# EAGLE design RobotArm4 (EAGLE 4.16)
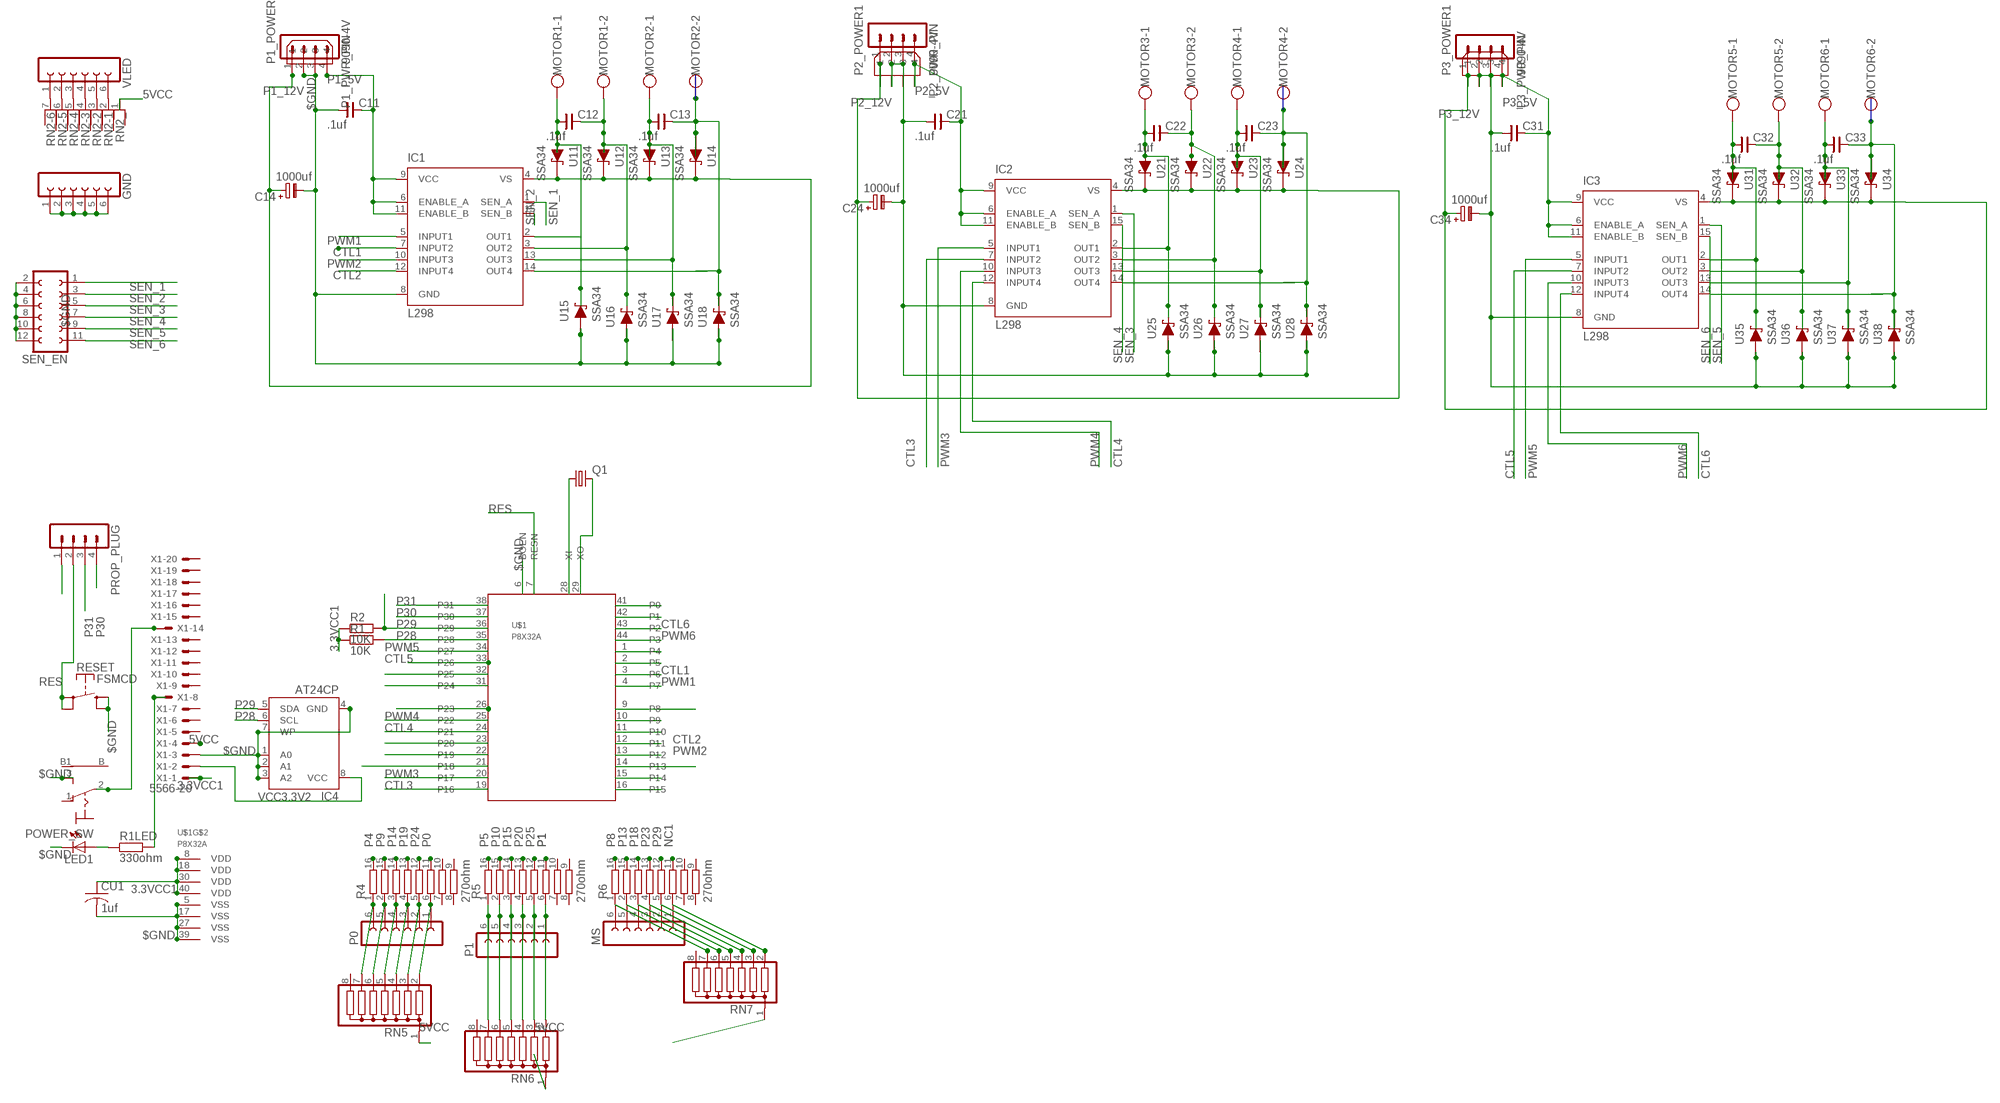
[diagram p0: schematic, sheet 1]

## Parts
C11  .1uf  CNP-1206  [1206]
C12  .1uf  CNP-1206  [1206]
C13  .1uf  CNP-1206  [1206]
C14  1000uf  C-PR-SMD-SV-C  [SV-C]
C21  .1uf  CNP-1206  [1206]
C22  .1uf  CNP-1206  [1206]
C23  .1uf  CNP-1206  [1206]
C24  1000uf  C-PR-SMD-SV-C  [SV-C]
C31  .1uf  CNP-1206  [1206]
C32  .1uf  CNP-1206  [1206]
C33  .1uf  CNP-1206  [1206]
C34  1000uf  C-PR-SMD-SV-C  [SV-C]
CU1  1uf  C-USC1206  [C1206]
GND  FE06-1  [FE06]
IC1  L298  [MULTIWATT-15]
IC2  L298  [MULTIWATT-15]
IC3  L298  [MULTIWATT-15]
IC4  AT24CP  [DIL08]
LED1  LED5MM  [LED5MM]
MOTOR1  W237-102  [W237-102]
MOTOR2  W237-102  [W237-102]
MOTOR3  W237-102  [W237-102]
MOTOR4  W237-102  [W237-102]
MOTOR5  W237-102  [W237-102]
MOTOR6  W237-102  [W237-102]
MS  FE06-1  [FE06]
P0  FE06-1  [FE06]
P1  FE06-1  [FE06]
P1_POWER  9090-4V  [9090-4V]
P1_PWR_PIN  MA04-1  [MA04-1]
P2_POWER1  9090-4V  [9090-4V]
P2_PWR_PIN  MA04-1  [MA04-1]
P3_POWER1  9090-4V  [9090-4V]
P3_PWR_PIN  MA04-1  [MA04-1]
POWER_SW  9070-1W  [9070-1W]
PROP_PLUG  MA04-1  [MA04-1]
Q1  CRYSTALHC49S  [HC49/S]
R1  10K  RESISTOR_1206  [RESC3115X70N]
R1LED  330ohm  RESISTOR_1206  [RESC3115X70N]
R2  10K  RESISTOR_1206  [RESC3115X70N]
R4  270ohm  2NBS16-8  [SO16]
R5  270ohm  2NBS16-8  [SO16]
R6  270ohm  2NBS16-8  [SO16]
RESET  FSMCD  [FSMCD]
RN2  RNX6  [RN-7]
RN5  G07R  [SIL8]
RN6  G07R  [SIL8]
RN7  G07R  [SIL8]
SEN_EN  FE06-2  [FE06-2]
U11  SSA34  [SMA]
U12  SSA34  [SMA]
U13  SSA34  [SMA]
U14  SSA34  [SMA]
U15  SSA34  [SMA]
U16  SSA34  [SMA]
U17  SSA34  [SMA]
U18  SSA34  [SMA]
U21  SSA34  [SMA]
U22  SSA34  [SMA]
U23  SSA34  [SMA]
U24  SSA34  [SMA]
U25  SSA34  [SMA]
U26  SSA34  [SMA]
U27  SSA34  [SMA]
U28  SSA34  [SMA]
U31  SSA34  [SMA]
U32  SSA34  [SMA]
U33  SSA34  [SMA]
U34  SSA34  [SMA]
U35  SSA34  [SMA]
U36  SSA34  [SMA]
U37  SSA34  [SMA]
U38  SSA34  [SMA]
U$1  P8X32A  [LQFP-44]
VLED  FE06-1  [FE06]
X1  5566-20  [5566-20]

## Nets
3.3VCC1: CU1.1 R1.1 R2.1 U$1.8(VDD) U$1.18(VDD) U$1.30(VDD) U$1.40(VDD) X1.1
5VCC: RN2.1 RN5.1 RN6.1 RN7.1 X1.4
$GND: C11.P$1 C14.- C21.P$1 C24.- C31.P$1 C34.- CU1.2 GND.1 GND.2 GND.3 GND.4 GND.5 GND.6 IC1.8(GND) IC2.8(GND) IC3.8(GND) IC4.1(A0) IC4.2(A1) IC4.3(A2) IC4.4(GND) IC4.7(WP) LED1.K(C) P1_POWER.2 P1_POWER.3 P1_PWR_PIN.2 P1_PWR_PIN.3 P2_POWER1.2 P2_POWER1.3 P2_PWR_PIN.2 P2_PWR_PIN.3 P3_POWER1.2 P3_POWER1.3 P3_PWR_PIN.2 P3_PWR_PIN.3 POWER_SW.3(S) PROP_PLUG.1 RESET.P$3(S) RESET.P$4(S) SEN_EN.2 SEN_EN.4 SEN_EN.6 SEN_EN.8 SEN_EN.10 SEN_EN.12 U15.2(A) U16.2(A) U17.2(A) U18.2(A) U25.2(A) U26.2(A) U27.2(A) U28.2(A) U35.2(A) U36.2(A) U37.2(A) U38.2(A) U$1.5(VSS) U$1.6(BOEN) U$1.17(VSS) U$1.27(VSS) U$1.39(VSS) X1.3
CTL1: IC1.7(INPUT2) U$1.3(P6)
CTL2: IC1.12(INPUT4) U$1.12(P11)
CTL3: IC2.7(INPUT2) U$1.19(P16)
CTL4: IC2.12(INPUT4) U$1.24(P21)
CTL5: IC3.7(INPUT2) U$1.33(P26)
CTL6: IC3.12(INPUT4) U$1.43(P2)
M5GND: C13.P$2 IC1.14(OUT4) MOTOR2.2 U14.2(A) U18.1(C)
M5GND1: C23.P$2 IC2.14(OUT4) MOTOR4.2 U24.2(A) U28.1(C)
M5GND2: C33.P$2 IC3.14(OUT4) MOTOR6.2 U34.2(A) U38.1(C)
M5VCC: C13.P$1 IC1.13(OUT3) MOTOR2.1 U13.2(A) U17.1(C)
M5VCC1: C23.P$1 IC2.13(OUT3) MOTOR4.1 U23.2(A) U27.1(C)
M5VCC2: C33.P$1 IC3.13(OUT3) MOTOR6.1 U33.2(A) U37.1(C)
M6GND: C12.P$2 IC1.3(OUT2) MOTOR1.2 U12.2(A) U16.1(C)
M6GND1: C22.P$2 IC2.3(OUT2) MOTOR3.2 U22.2(A) U26.1(C)
M6GND2: C32.P$2 IC3.3(OUT2) MOTOR5.2 U32.2(A) U36.1(C)
M6VCC: C12.P$1 IC1.2(OUT1) MOTOR1.1 U11.2(A) U15.1(C)
M6VCC1: C22.P$1 IC2.2(OUT1) MOTOR3.1 U21.2(A) U25.1(C)
M6VCC2: C32.P$1 IC3.2(OUT1) MOTOR5.1 U31.2(A) U35.1(C)
N$1: RN2.2 VLED.6
N$2: RN2.3 VLED.5
N$3: POWER_SW.2(P) X1.14
N$4: R1LED.2 X1.8
N$5: RN2.4 VLED.4
N$6: LED1.A R1LED.1
N$7: P1.1 R5.6 RN6.2
N$8: RN2.5 VLED.3
N$9: RN2.6 VLED.2
N$10: RN2.7 VLED.1
N$11: P1.2 R5.5 RN6.3
N$12: P0.3 R4.4 RN5.4
N$13: Q1.2 U$1.29(XO)
N$14: Q1.1 U$1.28(XI)
N$15: P0.4 R4.3 RN5.5
N$16: P0.5 R4.2 RN5.6
N$17: P0.6 R4.1 RN5.7
N$18: P1.3 R5.4 RN6.4
N$19: P1.4 R5.3 RN6.5
N$20: P1.5 R5.2 RN6.6
N$21: P1.6 R5.1 RN6.7
N$22: MS.6 R6.1 RN7.7
N$23: MS.5 R6.2 RN7.6
N$24: MS.4 R6.3 RN7.5
N$25: MS.3 R6.4 RN7.4
N$26: MS.2 R6.5 RN7.3
N$27: MS.1 R6.6 RN7.2
NC1: R6.11
P0: R4.11 U$1.41(P0)
P0_1: P0.1 R4.6 RN5.2
P0_2: P0.2 R4.5 RN5.3
P1: R5.11 U$1.42(P1)
P1_5V: C11.P$2 IC1.6(ENABLE_A) IC1.9(VCC) IC1.11(ENABLE_B) P1_POWER.4 P1_PWR_PIN.4
P1_12V: C14.+ IC1.4(VS) P1_POWER.1 P1_PWR_PIN.1 U11.1(C) U12.1(C) U13.1(C) U14.1(C)
P2_5V: C21.P$2 IC2.6(ENABLE_A) IC2.9(VCC) IC2.11(ENABLE_B) P2_POWER1.4 P2_PWR_PIN.4
P2_12V: C24.+ IC2.4(VS) P2_POWER1.1 P2_PWR_PIN.1 U21.1(C) U22.1(C) U23.1(C) U24.1(C)
P3_5V: C31.P$2 IC3.6(ENABLE_A) IC3.9(VCC) IC3.11(ENABLE_B) P3_POWER1.4 P3_PWR_PIN.4
P3_12V: C34.+ IC3.4(VS) P3_POWER1.1 P3_PWR_PIN.1 U31.1(C) U32.1(C) U33.1(C) U34.1(C)
P4: R4.16 U$1.1(P4)
P5: R5.16 U$1.2(P5)
P8: R6.16 U$1.9(P8)
P9: R4.15 U$1.10(P9)
P10: R5.15 U$1.11(P10)
P13: R6.15 U$1.14(P13)
P14: R4.14 U$1.15(P14)
P15: R5.14 U$1.16(P15)
P18: R6.14 U$1.21(P18)
P19: R4.13 U$1.22(P19)
P20: R5.13 U$1.23(P20)
P23: R6.13 U$1.26(P23)
P24: R4.12 U$1.31(P24)
P25: R5.12 U$1.32(P25)
P28: IC4.6(SCL) R1.2 U$1.35(P28)
P29: IC4.5(SDA) R2.2 R6.12 U$1.36(P29)
P30: PROP_PLUG.4 U$1.37(P30)
P31: PROP_PLUG.3 U$1.38(P31)
PWM1: IC1.5(INPUT1) U$1.4(P7)
PWM2: IC1.10(INPUT3) U$1.13(P12)
PWM3: IC2.5(INPUT1) U$1.20(P17)
PWM4: IC2.10(INPUT3) U$1.25(P22)
PWM5: IC3.5(INPUT1) U$1.34(P27)
PWM6: IC3.10(INPUT3) U$1.44(P3)
RES: PROP_PLUG.2 RESET.P$1(P) RESET.P$2(P) U$1.7(RESN)
SEN_1: IC1.1(SEN_A) SEN_EN.1
SEN_2: IC1.15(SEN_B) SEN_EN.3
SEN_3: IC2.1(SEN_A) SEN_EN.5
SEN_4: IC2.15(SEN_B) SEN_EN.7
SEN_5: IC3.1(SEN_A) SEN_EN.9
SEN_6: IC3.15(SEN_B) SEN_EN.11
VCC3.3V2: IC4.8(VCC) X1.2
Unconnected: POWER_SW.1(O) POWER_SW.B POWER_SW.B1 R4.7 R4.8 R4.9 R4.10 R5.7 R5.8 R5.9 R5.10 R6.7 R6.8 R6.9 R6.10 RN5.8 RN6.8 RN7.8 X1.5 X1.6 X1.7 X1.9 X1.10 X1.11 X1.12 X1.13 X1.15 X1.16 X1.17 X1.18 X1.19 X1.20

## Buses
B$1

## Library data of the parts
C11-C13 C21-C23 C31-C33 = zz-cap-master:CNP-: NON-POLARIZED CAP
C14 C24 C34 = zz-cap-pan40:C-PR: POLARIZED ELECTROLYTIC/TANTALUM
CU1 = zz-rcl:C-US: CAPACITOR, American symbol
GND MS P0 P1 VLED = con-lsta:FE06-1: FEMALE HEADER
IC1-IC3 = zz-st-microelectronics:L298: DUAL FULL-BRIDGE DRIVER
IC4 = atmel:AT24C*: 2-wire serial EEPROM
LED1 = led:LED: LED
MOTOR1-MOTOR6 = con-wago-500:W237-102: WAGO SCREW CLAMP
P1_POWER P2_POWER1 P3_POWER1 = con-thomas-betts:9090-4: Disk Drive Power four position Source: Thomas & Betts Electronic Interconnects Eiropean Edition 1998
P1_PWR_PIN P2_PWR_PIN P3_PWR_PIN PROP_PLUG = con-lstb:MA04-1: PIN HEADER
POWER_SW = switch:9070-1W: TOGGLE SWITCH Marquardt
Q1 = crystal:CRYSTAL: CRYSTAL
R1 R1LED R2 = zz-ipc-7351-resistor:RESISTOR_
R4-R6 = resistor-bourns:2NBS16-8: BOURNS RESISTOR NETWORK
RESET = zz-switch-misc:FSMCD: TYCO SWITCH
RN2 = resistor-net:RNX6: RESISTOR NETWORK
RN5-RN7 = resistor-sil:G07R: SIL RESISTOR
SEN_EN = con-lsta:FE06-2: FEMALE HEADER
U11-U18 U21-U28 U31-U38 = diode-20CJQ030:SSA34
U$1 = propeller:P8X32A
X1 = con-molex:5566-20: Mini FIT connector 20 pol ATX PC-Motherboard Power connector Source: http://www.molex.com

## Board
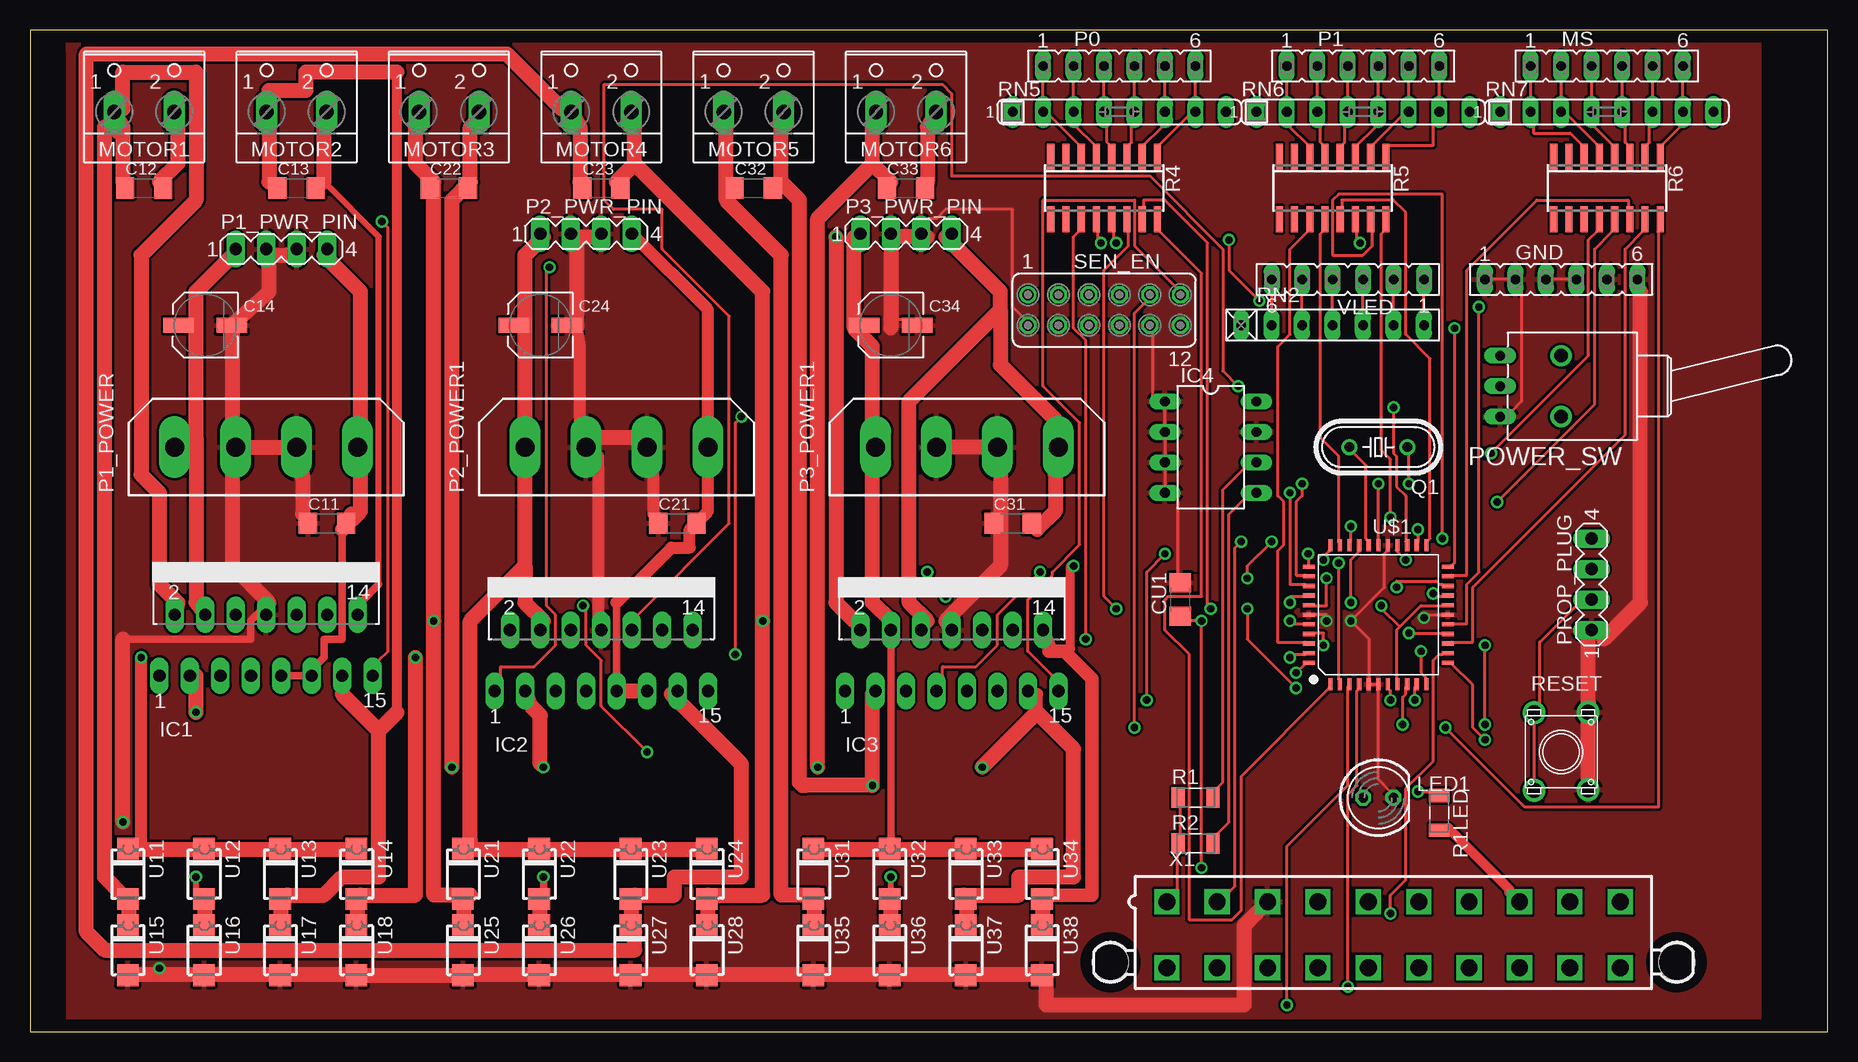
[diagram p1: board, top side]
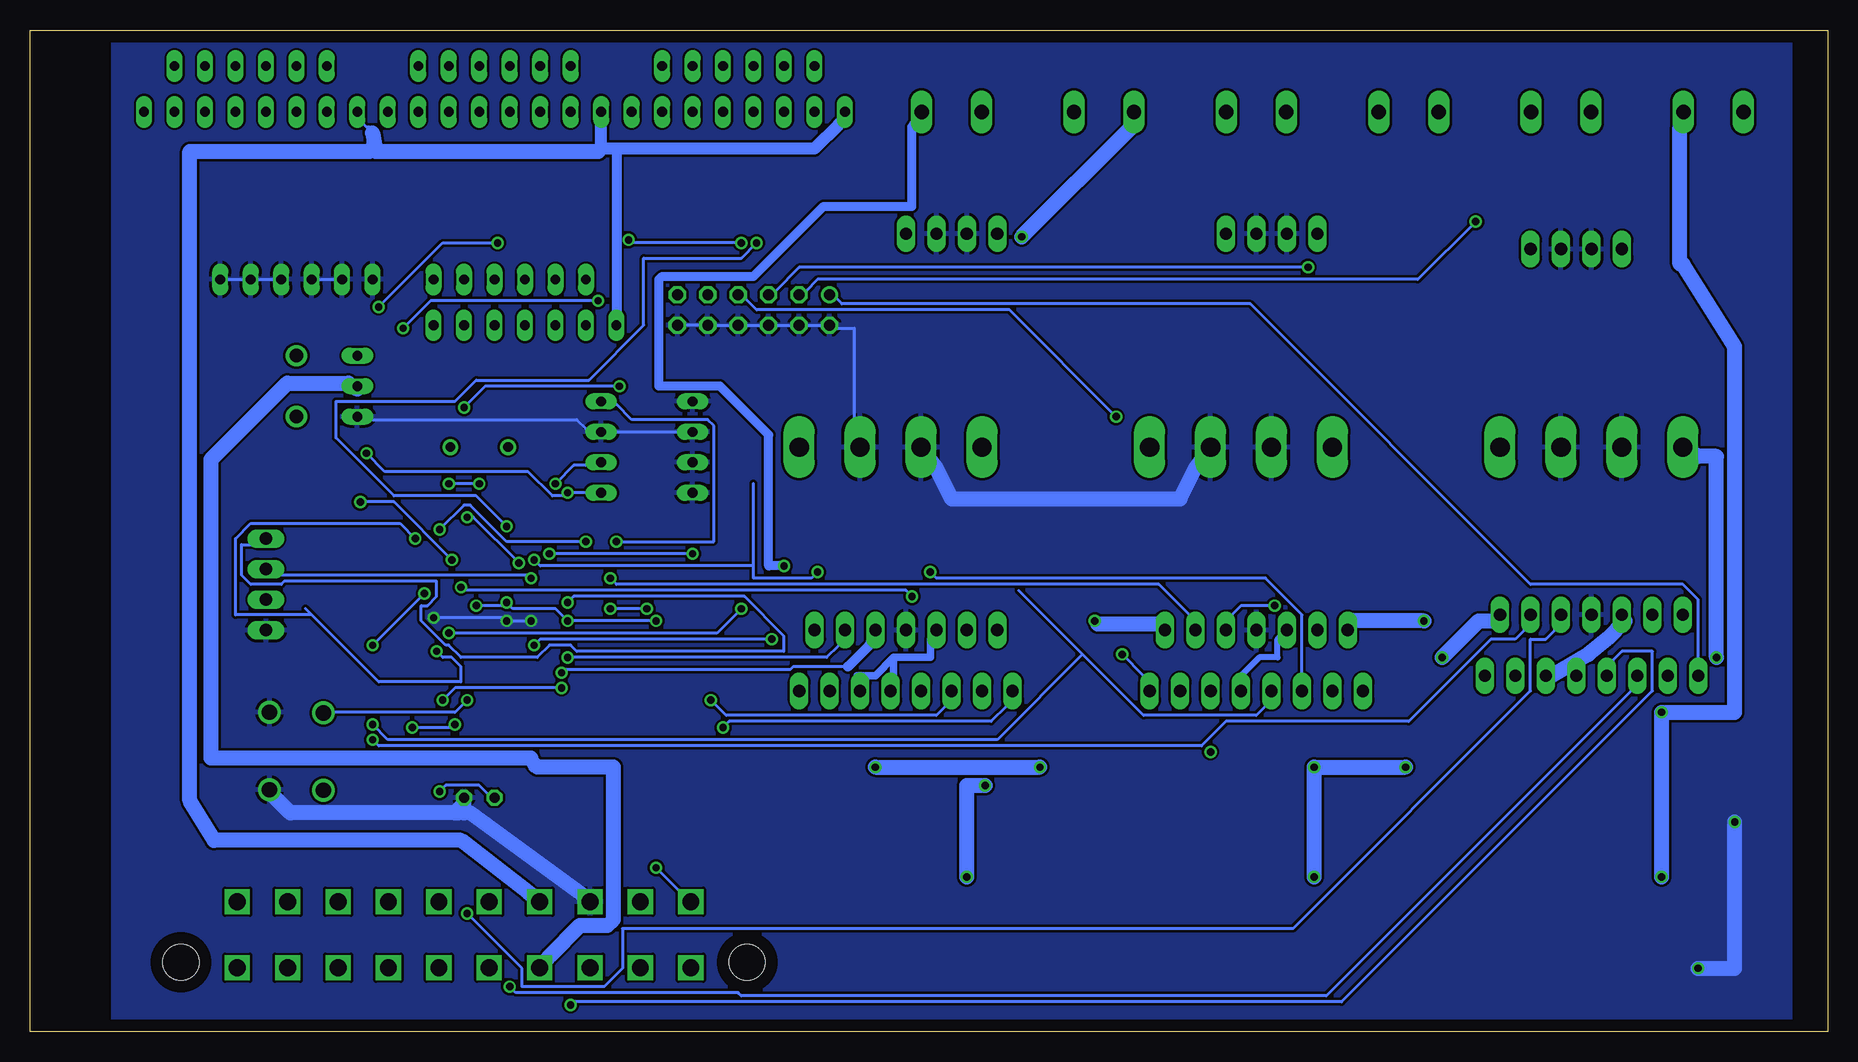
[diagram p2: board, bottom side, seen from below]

Size 149.84 x 83.49 mm. Coordinates in mm from the lower left corner, seen from the top.
Outline: 0,0 149.84,0 149.84,83.49 0,83.49 0,0
Copper layers (1*16): Top 0.035mm / dielectric 1.5mm / Bottom 0.035mm
Design rules "default": minimum track width 10mil, minimum drill 24mil, track to track 8mil, track to pad 8mil, pad to pad 8mil, via to via 8mil, smd to smd 8mil, copper to edge 40mil, drill to drill 8mil, minimum pad ring 10mil, minimum via ring 8mil, stop-mask expansion 4mil, vias tented up to drill 0mil, thermal gap 10mil

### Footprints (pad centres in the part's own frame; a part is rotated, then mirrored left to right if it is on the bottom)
1206 = smd 1.524 x 1.778: P$1 -1.587,0; P$2 1.587,0
SV-C = smd 2.54 x 1.27: + -2.223,0; - 2.223,0
C1206 = smd 1.6 x 1.8: 1 -1.4,0; 2 1.4,0
FE06 = drill 0.813 long: 1 -6.35,0; 2 -3.81,0; 3 -1.27,0; 4 1.27,0; 5 3.81,0; 6 6.35,0
MULTIWATT-15 = drill 1.016 long: 1 -8.89,-7.62; 2 -7.62,-2.54; 3 -6.35,-7.62; 4 -5.08,-2.54; 5 -3.81,-7.62; 6 -2.54,-2.54; 7 -1.27,-7.62; 8 0,-2.54; 9 1.27,-7.62; 10 2.54,-2.54; 11 3.81,-7.62; 12 5.08,-2.54; 13 6.35,-7.62; 14 7.62,-2.54; 15 8.89,-7.62
DIL08 = drill 0.813 long: 1 -3.81,-3.81; 2 -1.27,-3.81; 3 1.27,-3.81; 4 3.81,-3.81; 5 3.81,3.81; 6 1.27,3.81; 7 -1.27,3.81; 8 -3.81,3.81
LED5MM = drill 0.813 octagon: A -1.27,0; K 1.27,0
W237-102 = drill 1.194 long: 1 -2.5,-1.27; 2 2.5,-1.27
9090-4V = drill 1.6 pad 2.6 long: 1 -7.62,0; 2 -2.54,0; 3 2.54,0; 4 7.62,0
MA04-1 = drill 1.016 long: 1 -3.81,0; 2 -1.27,0; 3 1.27,0; 4 3.81,0
9070-1W = drill 0.813 long: 1 5.08,-2.54; 2 5.08,0; 3 5.08,2.54 | drill 1.118 pad 1.778 round: B 0,-2.54; B1 0,2.54
HC49/S = drill 0.813 round: 1 -2.413,0; 2 2.413,0
RESC3115X70N = smd 1.1 x 1.7: 1 -1.45,0; 2 1.45,0
SO16 = smd 0.6 x 2.2: 1 -4.445,-2.6; 2 -3.175,-2.6; 3 -1.905,-2.6; 4 -0.635,-2.6; 5 0.635,-2.6; 6 1.905,-2.6; 7 3.175,-2.6; 8 4.445,-2.6; 9 4.445,2.6; 10 3.175,2.6; 11 1.905,2.6; 12 0.635,2.6; 13 -0.635,2.6; 14 -1.905,2.6; 15 -3.175,2.6; 16 -4.445,2.6
FSMCD = drill 1.27 round: P$1 -2.25,3.25; P$2 -2.25,-3.2; P$3 2.25,3.3; P$4 2.25,-3.15
RN-7 = drill 0.813 long: 1 -7.62,0; 2 -5.08,0; 3 -2.54,0; 4 0,0; 5 2.54,0; 6 5.08,0; 7 7.62,0
SIL8 = drill 0.813 long: 1 -8.89,0; 2 -6.35,0; 3 -3.81,0; 4 -1.27,0; 5 1.27,0; 6 3.81,0; 7 6.35,0; 8 8.89,0
FE06-2 = drill 0.914 round: 1 -6.35,1.27 | drill 0.914 octagon: 2 -6.35,-1.27; 3 -3.81,1.27; 4 -3.81,-1.27; 5 -1.27,1.27; 6 -1.27,-1.27; 7 1.27,1.27; 8 1.27,-1.27; 9 3.81,1.27; 10 3.81,-1.27; 11 6.35,1.27; 12 6.35,-1.27
SMA = smd 1.8 x 1.8: 1 -2.1,-0.1; 2 2.1,-0.1
LQFP-44 = smd 0.35 x 1: 1 -4,-5.8; 2 -3.2,-5.8; 3 -2.4,-5.8; 4 -1.6,-5.8; 5 -0.8,-5.8; 6 0,-5.8; 7 0.8,-5.8; 8 1.6,-5.8; 9 2.4,-5.8; 10 3.2,-5.8; 11 4,-5.8; 23 4,5.8; 24 3.2,5.8; 25 2.4,5.8; 26 1.6,5.8; 27 0.8,5.8; 28 0,5.8; 29 -0.8,5.8; 30 -1.6,5.8; 31 -2.4,5.8; 32 -3.2,5.8; 33 -4,5.8 | smd 1 x 0.35: 12 5.8,-4; 13 5.8,-3.2; 14 5.8,-2.4; 15 5.8,-1.6; 16 5.8,-0.8; 17 5.8,0; 18 5.8,0.8; 19 5.8,1.6; 20 5.8,2.4; 21 5.8,3.2; 22 5.8,4; 34 -5.8,4; 35 -5.8,3.2; 36 -5.8,2.4; 37 -5.8,1.6; 38 -5.8,0.8; 39 -5.8,0; 40 -5.8,-0.8; 41 -5.8,-1.6; 42 -5.8,-2.4; 43 -5.8,-3.2; 44 -5.8,-4
5566-20 = drill 1.4 square: 1 18.9,-2.75; 2 14.7,-2.75; 3 10.5,-2.75; 4 6.3,-2.75; 5 2.1,-2.75; 6 -2.1,-2.75; 7 -6.3,-2.75; 8 -10.5,-2.75; 9 -14.7,-2.75; 10 -18.9,-2.75; 11 18.9,2.75; 12 14.7,2.75; 13 10.5,2.75; 14 6.3,2.75; 15 2.1,2.75; 16 -2.1,2.75; 17 -6.3,2.75; 18 -10.5,2.75; 19 -14.7,2.75; 20 -18.9,2.75 | hole 3: 23.6,2.29; -23.6,2.29

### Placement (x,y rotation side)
C11  24.76,42.38 0 top
C12  9.52,70.32 0 top
C13  22.22,70.32 0 top
C14  14.6,58.89 0 top
C21  53.97,42.38 0 top
C22  34.92,70.32 0 top
C23  47.62,70.32 0 top
C24  42.54,58.89 0 top
C31  81.91,42.38 0 top
C32  60.32,70.32 0 top
C33  73.02,70.32 0 top
C34  71.75,58.89 0 top
CU1  95.88,36.03 90 top
GND  127.63,62.7 0 top
IC1  19.68,37.3 0 top
IC2  47.62,36.03 0 top
IC3  76.83,36.03 0 top
IC4  98.42,48.73 270 top
LED1  112.39,19.52 0 top
MOTOR1  9.52,77.94 0 top
MOTOR2  22.22,77.94 0 top
MOTOR3  34.92,77.94 0 top
MOTOR4  47.62,77.94 0 top
MOTOR5  60.32,77.94 0 top
MOTOR6  73.02,77.94 0 top
MS  131.44,80.48 0 top
P0  90.8,80.48 0 top
P1  111.12,80.48 0 top
P1_POWER  19.68,48.73 0 top
P1_PWR_PIN  20.95,65.24 0 top
P2_POWER1  48.89,48.73 0 top
P2_PWR_PIN  46.35,66.51 0 top
P3_POWER1  78.1,48.73 0 top
P3_PWR_PIN  73.02,66.51 0 top
POWER_SW  127.63,53.81 180 top
PROP_PLUG  130.17,37.3 90 top
Q1  112.39,48.73 180 top
R1  97.15,19.52 0 top
R1LED  117.47,18.25 270 top
R2  97.15,15.71 0 top
R4  89.53,70.32 180 top
R5  108.58,70.32 180 top
R6  131.44,70.32 180 top
RESET  127.63,23.33 0 top
RN2  108.58,58.89 0 top
RN5  90.8,76.67 0 top
RN6  111.12,76.67 0 top
RN7  131.44,76.67 0 top
SEN_EN  89.53,60.16 0 top
U11  8.25,13.17 270 top
U12  14.6,13.17 270 top
U13  20.95,13.17 270 top
U14  27.3,13.17 270 top
U15  8.25,6.82 270 top
U16  14.6,6.82 270 top
U17  20.95,6.82 270 top
U18  27.3,6.82 270 top
U21  36.19,13.17 270 top
U22  42.54,13.17 270 top
U23  50.16,13.17 270 top
U24  56.51,13.17 270 top
U25  36.19,6.82 270 top
U26  42.54,6.82 270 top
U27  50.16,6.82 270 top
U28  56.51,6.82 270 top
U31  65.4,13.17 270 top
U32  71.75,13.17 270 top
U33  78.1,13.17 270 top
U34  84.45,13.17 270 top
U35  65.4,6.82 270 top
U36  71.75,6.82 270 top
U37  78.1,6.82 270 top
U38  84.45,6.82 270 top
U$1  112.39,34.76 0 top
VLED  109.85,62.7 180 top
X1  113.66,8.09 180 top

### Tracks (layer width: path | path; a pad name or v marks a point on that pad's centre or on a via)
3.3VCC1  (via drill 0.61)
  Top 0.254: R1.1 95.88,18.76 95.88,16.47 R2.1 95.63,14.95 95.63,11.65 X1.1 | 114.17,33.74 115.95,35.52 117.72,35.52 U$1.18 | 114.17,33.74 113.91,33.49 113.91,29.43 U$1.8 | v105.02,34.25 105.02,34 106.29,34 U$1.40 | CU1.1 96.64,34.25 v97.66,34.25 v97.66,13.68 | v110.1,35.78 110.1,39.33 110.87,40.09 U$1.30 | 114.17,33.74 112.64,35.27 v112.64,35.52
  Bottom 0.254: v97.66,34.25 v105.02,34.25 106.04,35.27 109.6,35.27 v110.1,35.78 110.36,35.52 v112.64,35.52 | v97.66,13.68 95.63,11.65 X1.1
5VCC
  Bottom 0.254: 82.42,75.65 RN5.1 | 101.98,73.62 102.48,73.37 102.23,73.88 | RN7.1 122.04,75.65 121.79,75.4 121.53,75.4 121.28,74.89
  Bottom 0.762: 121.53,73.37 121.28,74.89
  Bottom 0.813: 100.96,73.62 RN2.1
  Bottom 1.016: 82.42,75.65 84.45,73.62 100.96,73.62 101.98,73.62 | 102.23,73.88 RN6.1
  Bottom 1.27: 121.53,73.37 136.52,73.37 136.52,19.27 134.49,15.96 113.91,15.96 108.33,11.65 X1.4 | 102.48,73.37 121.03,73.37 121.28,74.89
$GND  (via drill 0.61)
  Top 0.254: 66.16,4.79 U35.2 64.64,4.79 | 70.99,4.79 U36.2 72.51,4.79 | 78.86,4.79 U37.2 77.34,4.79 | 83.69,4.79 U38.2 85.21,5.55 | U25.2 36.95,4.79 | 41.78,4.79 U26.2 43.3,4.79 | 50.92,4.79 U27.2 49.4,4.79 | 55.75,4.79 U28.2 57.27,4.79 | U15.2 9.01,4.79 | 13.84,4.79 U16.2 15.36,4.79 | 21.71,4.79 U17.2 20.19,4.79 | 26.54,4.79 U18.2 26.54,5.55 | RESET.P$4 129.92,21.04 | 129.92,25.87 RESET.P$3 129.92,27.39 | 16.89,47.21 17.14,50.76 | 16.89,46.19 P1_POWER.2 | 45.71,57.89 45.59,57.87 C24.- | 71.75,59.4 73.27,59.4 C34.- | P3_PWR_PIN.3 74.8,67.78 75.56,67.78 76.32,68.54 81.91,68.54 81.91,60.41 82.93,59.4 SEN_EN.2 | CU1.2 95.63,38.06 95.63,44.41 IC4.4 IC4.3 IC4.2 IC4.1 93.59,53.05 93.59,58.38 SEN_EN.10 | v108.07,34.25 108.07,34.76 U$1.39 | U$1.27 113.15,40.09 112.9,39.84 112.9,37.05 v110.1,34.25 111.63,32.73 111.63,29.43 U$1.5 111.63,28.92 112.39,28.92 U$1.6 112.39,21.04 113.41,20.03 LED1.K | v116.2,34.51 116.2,34.76 U$1.17 | GND.4 GND.3 | POWER_SW.3 123.57,51.78 124.33,52.54 124.33,61.68 GND.2 GND.1 | 129.92,32.98 PROP_PLUG.1 131.44,33.49 131.69,33.24
  Top 0.406: U25.2 36.19,4.72 36.19,4.28
  Top 0.508: P3_PWR_PIN.3 74.8,66.26 | 71.75,66.26 P3_PWR_PIN.2 | 16.89,47.21 16.89,46.19 16.89,46.44 | 47.37,66.26 P2_PWR_PIN.3 | 45.59,66.26 P2_PWR_PIN.2 | 47.37,34.25 IC2.8 | 10.79,4.79 v10.79,5.3
  Top 0.61: 7.74,32.73 18.41,32.73 18.41,34.25 19.93,35.78 IC1.8 | P1_POWER.2 P1_POWER.3 P1_POWER.2 | P1_POWER.2 17.14,50.76 17.14,51.27 | P1_POWER.2 17.14,46.19
  Top 0.762: RESET.P$4 129.66,19.77 | U38.2 84.7,4.53
  Top 0.813: 51.94,43.14 C21.P$1 | 19.93,64.73 P1_PWR_PIN.2
  Top 1.016: 21.46,64.73 P1_PWR_PIN.3 | P2_PWR_PIN.2 45.84,66.26 | 51.94,43.14 51.94,46.44 P2_POWER1.3 50.41,49.49 | 47.37,34.25 47.37,47.97 P2_POWER1.2 | 47.37,49.49 P2_POWER1.2 | 45.59,58.64 45.71,57.89 45.84,57.11 45.84,51.02 P2_POWER1.2 | 134.23,61.68 GND.6 | 22.73,43.14 C11.P$1
  Top 1.27: 66.16,4.79 70.99,4.79 | 78.86,4.79 83.69,4.79 | 72.51,4.79 77.34,4.79 | 36.95,4.79 41.78,4.79 | 50.92,4.79 55.75,4.79 | 43.3,4.79 49.4,4.79 | 9.01,4.79 10.79,4.79 13.84,4.79 | 21.71,4.79 26.54,4.79 | 15.36,4.79 20.19,4.79 | U18.2 36.19,4.72 | 129.92,21.04 129.92,25.87 | 129.92,27.39 129.92,32.98 | 74.8,66.26 71.75,66.26 71.75,59.4 71.75,58.64 | 80.89,41.87 80.89,46.44 P3_POWER1.3 P3_POWER1.2 | 80.89,41.87 80.89,38.82 76.32,34.25 IC3.8 | 80.89,41.87 C31.P$1 | 21.46,64.73 19.93,64.73 19.93,61.68 C14.- 16.89,58.64 16.89,47.21 16.89,38.82 19.93,35.78 | 45.84,66.26 47.37,66.26 | 45.59,58.64 45.59,66.26 | 50.41,49.49 47.37,49.49 | 134.23,61.68 134.23,35.78 131.69,33.24 131.19,32.73 | v7.74,17.49 7.74,32.73 | 57.27,4.79 64.64,4.79 | P1_POWER.2 P1_POWER.3 22.73,46.19 22.73,43.14 | 84.7,4.53 84.7,2.25 101.21,2.25 101.21,8.85 102.23,9.87 X1.3
  Bottom 0.254: SEN_EN.12 SEN_EN.10 SEN_EN.8 SEN_EN.6 SEN_EN.4 SEN_EN.2 82.67,58.64 81.15,58.64 81.15,51.27 P3_POWER1.3 | IC4.2 IC4.7 103.5,50.25 104.26,51.02 121.28,51.02 POWER_SW.3 | v108.07,34.25 v110.1,34.25 110.36,34.51 v116.2,34.51 | GND.6 GND.5 GND.4 | GND.3 GND.2
  Bottom 0.762: 113.66,19.01 LED1.K | 129.66,19.77 RESET.P$4 | 113.66,18.25 114.04,18.63
  Bottom 1.27: v7.74,17.49 7.74,5.3 v10.79,5.3 | P3_POWER1.2 74.29,46.95 73.02,44.41 53.97,44.41 52.7,46.95 P2_POWER1.3 | 114.17,18.25 113.66,18.25 113.15,18.25 103.75,11.39 X1.3 | 113.66,19.01 114.04,18.63 114.42,18.25 128.14,18.25 129.66,19.77
  pour Bottom: 3.17,83.02 3.17,0.47 142.87,0.47 142.87,14.44 142.87,83.02
  pour Top: 3.17,83.02 3.17,0.47 144.14,0.47 144.14,1.74 144.14,83.02 3.17,83.02 3.17,81.75
CTL1  (via drill 0.61)
  Top 0.254: v104.77,2.25 104.77,15.46 109.85,20.54 109.85,28.66 U$1.3
  Bottom 0.254: v104.77,2.25 104.52,2.5 40.51,2.5 14.6,28.41 14.6,31.71 17.14,31.71 17.9,30.95 IC1.7
CTL2  (via drill 0.61)
  Top 0.254: v121.28,24.35 120.26,25.36 120.26,28.92 118.49,30.7 U$1.12
  Bottom 0.254: IC1.12 25.27,33.49 26.03,32.73 28.06,32.73 34.92,25.87 50.16,25.87 52.19,23.84 120.77,23.84 v121.28,24.35
CTL3  (via drill 0.61)
  Top 0.254: v116.96,36.54 116.96,36.28 117.72,36.28 U$1.19 | v121.28,25.62 v121.28,32.22
  Bottom 0.254: 62.1,31.46 57.02,26.38 47.62,26.38 46.86,27.14 IC2.7 | 62.1,31.46 67.43,36.79 | v121.28,32.22 v116.96,36.54 | v121.28,25.62 120.01,24.35 69.21,24.35 62.1,31.46
CTL4  (via drill 0.61)
  Top 0.254: v115.69,41.87 115.69,40.86 U$1.24 | v103.5,40.86 101.47,38.82 v101.47,37.81
  Bottom 0.254: v115.69,41.87 113.66,43.9 113.15,43.9 110.1,40.86 v103.5,40.86 | v101.47,37.81 100.96,37.3 55.75,37.3 53.21,34.76 IC2.12
CTL5  (via drill 0.61)
  Top 0.254: v84.2,38.32 80.64,34.76 80.64,32.22 78.86,30.44 76.07,30.44 76.07,29.68 IC3.7 | v107.82,39.33 107.82,39.59 108.33,40.09 U$1.33
  Bottom 0.254: 89.53,38.82 89.53,37.81 84.7,37.81 v84.2,38.32 | 89.53,38.82 89.53,45.68 | v107.82,39.33 107.31,38.82 89.53,38.82
CTL6  (via drill 0.61)
  Top 0.254: v105.02,31.2 105.02,31.46 106.29,31.46 U$1.43
  Bottom 0.254: IC3.12 82.42,32.22 83.43,31.2 v105.02,31.2
M5GND  (via drill 0.61)
  Top 0.254: U18.1 27.3,9.61 | 27.3,10.38 U14.2
  Top 0.508: U14.2 27.55,11.39 | 29.08,37.3 29.08,66.26 24.51,70.83 C13.P$2
  Top 0.61: 29.08,37.3 27.55,35.78 IC1.14
  Top 1.27: 27.3,9.61 27.3,10.38 | 24.51,70.83 24.51,75.4 MOTOR2.2 | 27.55,11.39 32.13,11.39 v32.13,31.2
  Bottom 0.61: 27.55,34.25 IC1.14
  Bottom 1.27: v32.13,31.2 29.08,34.25 27.55,34.25
M5GND1  (via drill 0.61)
  Top 0.254: U28.1 56.51,9.61 | 56.51,10.38 U24.2
  Top 0.508: 48.89,70.83 C23.P$2 | U24.2 56.51,11.39
  Top 1.016: 50.41,75.4 MOTOR4.2
  Top 1.27: 56.51,9.61 56.51,10.38 | 50.41,72.35 48.89,70.83 | 50.41,72.35 50.41,75.4 | 56.51,11.39 61.08,11.39 v61.08,34.25 61.08,61.68 50.41,72.35
  Bottom 0.254: v61.08,34.25 60.83,34
  Bottom 1.27: 60.83,34 55.75,34 IC2.14
M5GND2  (via drill 0.61)
  Top 0.254: U38.1 84.45,9.61 | 84.45,10.38 U34.2
  Top 0.762: v86.99,38.82 86.74,38.82 86.74,31.97 86.36,31.59
  Top 1.143: U34.2 85.21,11.39 88.51,11.39 88.51,29.43 86.36,31.59 86.23,31.71 84.96,31.71 84.96,32.22 IC3.14
  Top 1.27: 84.45,9.61 84.45,10.38 | C33.P$2 74.8,70.83 74.8,75.4 MOTOR6.2
  Bottom 0.508: IC3.14 83.94,32.73
  Bottom 0.762: v86.99,38.82 88.26,38.82 88.26,49.75 92.32,53.81 97.4,53.81 97.4,62.7 97.15,62.95 89.53,62.95 83.69,68.8 76.32,68.8 76.32,75.4 MOTOR6.2
M5VCC
  Top 0.254: U17.1 20.95,9.61 | 20.95,10.38 U13.2
  Top 0.508: 19.93,70.83 C13.P$1 | U13.2 21.46,11.39
  Top 0.813: 26.03,28.16 IC1.13 | 30.6,26.63 30.6,79.97
  Top 1.27: 20.95,9.61 20.95,10.38 | 19.93,70.83 19.93,75.4 MOTOR2.1 19.93,78.45 22.98,78.45 22.98,79.97 30.6,79.97 | 21.46,11.39 24.51,11.39 26.03,12.92 29.08,12.92 29.08,25.11 | 29.08,25.11 26.03,28.16 | 29.08,25.11 30.6,26.63
M5VCC1
  Top 0.254: U27.1 50.16,9.61 | 50.16,10.38 U23.2
  Top 0.508: 45.84,70.83 C23.P$1 | U23.2 50.41,11.39 | 50.41,8.34 U27.1
  Top 0.61: 53.46,28.16 IC2.13
  Top 1.016: 44.32,76.92 MOTOR4.1
  Top 1.27: 50.16,9.61 50.16,10.38 | 45.84,70.83 45.84,75.4 MOTOR4.1 | 50.41,11.39 53.72,11.39 53.72,12.92 59.3,12.92 59.3,22.31 53.46,28.16 | 44.32,76.92 39.75,81.5 4.69,81.5 4.69,8.34 6.22,6.82 50.41,6.82 50.41,8.34
M5VCC2  (via drill 0.61)
  Top 0.254: U37.1 78.1,9.61 | 78.1,10.38 U33.2
  Top 0.508: 71.75,70.83 C33.P$1 | U33.2 77.85,11.39
  Top 1.016: 83.94,26.63 83.94,28.16 IC3.13
  Top 1.27: 78.1,9.61 78.1,10.38 | 70.23,72.35 71.75,70.83 | 70.23,72.35 70.23,75.4 MOTOR6.1 | 77.85,11.39 82.42,11.39 82.42,12.92 86.99,12.92 86.99,23.58 83.94,26.63 v79.37,22.06 | 70.23,72.35 65.65,67.78 v65.65,22.06
  Bottom 1.27: v79.37,22.06 v65.65,22.06
M6GND  (via drill 0.61)
  Top 0.254: U16.1 14.6,9.61 | 14.6,10.38 U12.2
  Top 0.508: 10.79,70.83 C12.P$2 | v13.84,12.92 13.84,11.39 U12.2
  Top 0.813: MOTOR1.2 12.31,75.4
  Top 1.016: 13.84,29.68 IC1.3
  Top 1.27: 14.6,9.61 14.6,10.38 | 10.79,70.83 12.31,72.35 12.31,75.4 | v13.84,26.63 13.84,29.68
  Bottom 0.508: 12.31,75.4 MOTOR1.2
  Bottom 0.61: 12.06,63.97 12.31,63.97
  Bottom 1.27: v13.84,12.92 v13.84,26.63 7.74,26.63 7.74,57.11 12.06,63.97 | 12.31,63.97 12.31,75.4
M6GND1  (via drill 0.61)
  Top 0.254: U26.1 42.54,9.61 | 42.54,10.38 U22.2 | v42.79,22.06 42.54,22.31
  Top 0.508: U22.2 42.79,11.39 | 36.7,70.83 C22.P$2
  Top 0.61: 42.79,11.39 v42.79,12.92
  Top 1.016: 36.7,75.4 MOTOR3.2
  Top 1.27: 42.54,9.61 42.54,10.38 | 36.7,75.4 36.7,70.83 35.17,69.3 v35.17,22.06 | 42.54,22.31 42.54,26.38 41.78,27.14 IC2.3
  Bottom 1.27: v42.79,12.92 v42.79,22.06 v35.17,22.06
M6GND2  (via drill 0.61)
  Top 0.254: U36.1 71.75,9.61 | 71.75,10.38 U32.2 | 64.64,20.54 64.13,20.79
  Top 0.508: v71.75,12.92 71.75,11.39 U32.2 | 70.23,28.16 IC3.3 | 62.61,70.83 C32.P$2
  Top 1.016: 62.61,75.4 MOTOR5.2
  Top 1.27: 71.75,9.61 71.75,10.38 | 62.61,75.4 62.61,70.83 64.13,69.3 64.13,20.79 | 70.23,28.16 v70.23,20.54 64.64,20.54 64.38,20.54
  Bottom 1.27: v71.75,12.92 71.75,20.54 v70.23,20.54
M6VCC
  Top 0.254: C12.P$1 7.23,71.08 | U15.1 8.25,9.61 | 8.25,10.38 U11.2
  Top 0.508: 7.74,70.83 C12.P$1 | U11.2 7.74,11.39 | 6.22,75.4 MOTOR1.1
  Top 0.813: MOTOR1.1 7.74,76.92
  Top 1.016: MOTOR1.1 7.23,74.89
  Top 1.27: 8.25,9.61 8.25,10.38 | 7.74,70.83 7.74,75.4 MOTOR1.1 | 7.74,11.39 6.22,12.92 6.22,75.4 | 7.74,76.92 7.74,79.97 13.84,79.97 13.84,69.3 9.27,64.73 9.27,46.44 10.79,44.92 10.79,37.3 12.31,35.78 IC1.2
M6VCC1  (via drill 0.61)
  Top 0.254: U25.1 36.19,9.61 | 36.19,10.38 U21.2
  Top 0.508: U21.2 36.7,11.39 | 33.65,70.83 C22.P$1
  Top 1.016: 32.13,75.4 MOTOR3.1
  Top 1.27: 36.19,9.61 36.19,10.38 | 32.13,75.4 32.13,72.35 33.65,70.83 v33.65,34.25 33.65,11.39 36.7,11.39
  Bottom 0.508: 39.75,34.25 IC2.2
  Bottom 1.27: v33.65,34.25 39.75,34.25
M6VCC2  (via drill 0.61)
  Top 0.254: U35.1 65.4,9.61 | 65.4,10.38 U31.2
  Top 0.508: U31.2 65.65,11.39 | 58.03,70.83 C32.P$1
  Top 0.813: 68.7,34.25 IC3.2
  Top 1.016: 58.03,75.4 MOTOR5.1
  Top 1.27: 65.4,9.61 65.4,10.38 | 58.03,75.4 58.03,70.83 58.03,69.3 62.61,64.73 62.61,11.39 65.65,11.39 | 68.7,34.25 67.18,35.78 v67.18,66.26
  Bottom 0.508: MOTOR5.1 58.03,75.4
  Bottom 1.27: 58.03,75.4 v67.18,66.26
N$1
  Top 0.254: RN2.2 VLED.6
N$2
  Top 0.254: RN2.3 VLED.5
N$3
  Bottom 0.762: 122.67,53.63 POWER_SW.2 | 107.82,22.31 108.07,22.82
  Bottom 1.27: 122.55,53.56 122.67,53.63 123.31,54.06 128.39,54.06 134.74,47.71 134.74,22.82 108.07,22.82 | X1.14 106.55,6.31 104.01,8.85 101.72,8.85 101.21,9.36 101.21,22.06 107.56,22.06 107.82,22.31
N$4
  Top 0.254: 123.31,11.9 123.31,11.65 | R1LED.2 117.98,16.98 118.23,16.98
  Top 0.813: 118.23,16.98 123.31,11.9 | 123.31,11.65 X1.8
N$5
  Top 0.254: RN2.4 VLED.4
N$6  (via drill 0.61)
  Top 0.254: v115.69,20.03 116.71,20.03 R1LED.1
  Bottom 0.254: v115.69,20.03 115.18,20.54 112.39,20.54 111.63,19.77 LED1.A
N$7
  Top 0.254: R5.6 106.55,73.88 105.02,75.4 RN6.2 P1.1
N$8
  Top 0.254: RN2.5 VLED.3
N$9
  Top 0.254: RN2.6 VLED.2
N$10
  Top 0.254: RN2.7 VLED.1
N$11
  Top 0.254: R5.5 107.82,73.88 107.56,74.13 107.56,75.4 RN6.3 P1.2
N$12
  Top 0.254: R4.4 90.04,73.88 89.78,74.13 89.78,75.4 RN5.4 P0.3
N$13
  Top 0.254: U$1.29 111.63,40.86 111.37,41.11 111.37,47.21 110.36,48.22 Q1.2
N$14  (via drill 0.61)
  Top 0.254: v114.93,45.68 114.93,48.22 Q1.1 | U$1.28 v112.39,45.68
  Bottom 0.254: v112.39,45.68 v114.93,45.68
N$15
  Top 0.254: R4.3 91.56,73.88 91.82,74.13 91.82,75.4 RN5.5 P0.4
N$16
  Top 0.254: R4.2 92.83,73.88 94.36,75.4 RN5.6 P0.5
N$17
  Top 0.254: R4.1 94.1,73.88 96.64,76.42 RN5.7 P0.6
N$18
  Top 0.254: R5.4 109.34,73.88 109.6,74.13 109.6,75.4 RN6.4 P1.3
N$19
  Top 0.254: R5.3 110.61,73.88 112.14,75.4 RN6.5 P1.4
N$20
  Top 0.254: R5.2 111.88,73.88 114.42,76.42 RN6.6 P1.5
N$21
  Top 0.254: R5.1 113.15,73.88 116.96,73.88 116.96,75.65 RN6.7 P1.6
N$22
  Top 0.254: MS.6 RN7.7 137.54,75.4 136.01,73.88 R6.1
N$23
  Top 0.254: MS.5 RN7.6 135,75.4 135,74.13 134.74,73.88 R6.2
N$24
  Top 0.254: MS.4 RN7.5 132.96,75.4 132.96,74.13 133.22,73.88 R6.3
N$25
  Top 0.254: MS.3 RN7.4 130.42,75.4 131.95,73.88 R6.4
N$26
  Top 0.254: MS.2 RN7.3 128.14,76.42 130.68,73.88 R6.5
N$27
  Top 0.254: MS.1 RN7.2 125.34,75.4 125.34,74.89 128.39,74.89 129.41,73.88 R6.6
P0  (via drill 0.61)
  Top 0.254: v107.82,32.22 107.82,33.24 107.06,33.24 U$1.41 | v88.01,32.73 88.01,57.62 86.99,58.64 86.99,66.26 87.5,66.76 R4.11
  Bottom 0.254: v107.82,32.22 107.31,32.73 v88.01,32.73
P0_1
  Top 0.254: R4.6 87.5,73.88 84.96,76.42 RN5.2 P0.1
P0_2
  Top 0.254: R4.5 88.77,73.88 87.24,75.4 RN5.3 P0.2
P1
  Top 0.254: U$1.42 106.29,32.47 104.01,32.47 104.01,40.09 104.52,40.6 104.52,44.16 104.01,44.67 104.01,57.11 105.02,58.13 105.02,65.24 106.55,66.76 R5.11
P1_5V
  Top 0.254: C11.P$2 25.78,41.62
  Top 0.508: 24.51,64.73 P1_PWR_PIN.4 | IC1.11 22.98,29.68 | 26.03,41.87 C11.P$2
  Top 0.61: IC1.9 22.98,29.68 24.51,31.2 24.51,32.73 26.03,32.73 26.03,41.87
  Top 1.27: C11.P$2 26.79,43.14 | 26.03,41.87 27.55,43.4 27.55,46.44 P1_POWER.4 27.55,51.02 27.55,61.68 24.51,64.73
  Bottom 0.508: 22.98,29.68 IC1.11
  Bottom 0.61: 16.89,34.25 IC1.6
  Bottom 1.27: 16.89,34.25 18.41,32.73 19.93,31.46 22.98,29.68
P1_12V  (via drill 0.61)
  Top 0.254: U11.1 9.01,15.2 | 13.84,15.2 U12.1 15.36,15.2 | 21.71,15.2 U13.1 20.19,15.2 | 26.54,15.2 U14.1 | 13.84,58.89 C14.+
  Top 1.016: 16.89,64.73 P1_PWR_PIN.1 | 9.27,15.2 v9.27,31.2
  Top 1.27: 9.01,15.2 9.27,15.2 13.84,15.2 | 21.71,15.2 26.54,15.2 | 15.36,15.2 20.19,15.2 | 13.84,49.49 13.84,35.78 IC1.4 | 16.89,64.73 13.84,61.68 13.84,58.89 13.84,49.49 | 13.84,49.49 12.31,49.49 P1_POWER.1
  Bottom 1.27: v9.27,31.2 9.27,47.97 10.79,47.97 P1_POWER.1
P2_5V
  Top 0.508: IC2.9 48.89,28.16
  Top 0.61: IC2.9 48.89,35.78
  Top 0.813: 54.99,41.87 C21.P$2
  Top 1.016: P2_PWR_PIN.4 56.51,60.16 P2_POWER1.4 56.51,43.4 54.99,41.87 54.99,40.35 53.46,40.35 48.89,35.78
  Top 1.27: IC2.9 IC2.11
  Bottom 0.508: IC2.6 45.84,32.73 45.84,31.2 47.37,31.2 48.89,29.68 IC2.9
P2_12V
  Top 0.254: U21.1 36.95,15.2 | 41.78,15.2 U22.1 | 50.92,15.2 U23.1 49.4,15.2 | 55.75,15.2 U24.1 | U22.1 43.3,15.2 | U22.1 42.54,15.96 | 41.27,58.89 C24.+
  Top 0.508: 42.79,66.26 P2_PWR_PIN.1 | 42.79,34.25 IC2.4 | U21.1 36.7,15.96
  Top 1.27: 36.95,15.2 41.78,15.2 | 50.92,15.2 55.75,15.2 | 43.3,15.2 49.4,15.2 | 42.79,66.26 41.27,64.73 41.27,58.89 P2_POWER1.1 41.27,38.82 | 42.79,34.25 41.27,35.78 41.27,38.82 | 36.7,15.96 36.7,34.25 41.27,38.82
P3_5V
  Top 0.508: 76.32,66.26 P3_PWR_PIN.4
  Top 0.813: 83.94,41.87 C31.P$2 | IC3.6 74.8,34.25
  Top 1.27: 83.94,41.87 85.47,43.4 85.47,46.44 P3_POWER1.4 85.47,51.02 80.89,55.59 80.89,60.16 | 76.32,66.26 80.89,61.68 80.89,60.16 | 74.8,34.25 73.27,35.78 73.27,52.54 80.89,60.16
  Bottom 0.508: 74.8,32.73 IC3.6
  Bottom 0.61: 74.8,32.73 74.8,31.2 77.85,31.2 | 77.85,31.2 79.37,29.68 80.89,29.68 IC3.11 | 77.85,31.2 77.85,29.68 IC3.9
P3_12V
  Top 0.254: U31.1 66.16,15.2 | 70.99,15.2 U32.1 72.51,15.2 | 78.86,15.2 U33.1 77.34,15.2 | 83.69,15.2 U34.1 | 68.83,58.51 C34.+
  Top 0.508: 68.7,66.26 P3_PWR_PIN.1 | IC3.4 71.75,34.25 | U32.1 71.75,15.96
  Top 0.61: 71.75,15.96 IC3.4
  Top 0.813: P3_POWER1.1 70.23,51.02
  Top 1.27: 66.16,15.2 70.99,15.2 | 78.86,15.2 83.69,15.2 | 72.51,15.2 77.34,15.2 | 68.7,66.26 68.7,58.64 68.83,58.51 70.23,57.11 70.23,51.02 | 71.75,34.25 70.23,35.78 70.23,46.44 P3_POWER1.1
P4
  Top 0.254: U$1.1 108.33,28.66 100.96,21.3 100.96,10.12 100.2,9.36 96.64,9.36 96.64,31.46 94.61,33.49 94.61,36.03 94.86,36.28 97.66,36.28 97.66,63.21 94.1,66.76 R4.16
P5  (via drill 0.61)
  Top 0.254: v109.09,39.08 109.09,29.43 U$1.2 | v113.41,42.89 113.41,47.71 112.64,48.48 112.64,66.51 112.9,66.76 R5.16
  Bottom 0.254: v109.09,39.08 112.9,42.89 v113.41,42.89
P8  (via drill 0.61)
  Top 0.254: v114.42,25.62 114.42,27.9 114.68,28.16 114.68,28.66 U$1.9 | v117.98,25.36 124.58,18.76 135.76,18.76 135.76,66.76 R6.16
  Bottom 0.254: v114.42,25.62 114.68,25.36 v117.98,25.36
P9  (via drill 0.61)
  Top 0.254: v115.44,27.65 115.44,28.66 U$1.10 | v105.53,28.66 101.47,32.73 v101.47,35.27 | v98.42,35.27 98.17,35.52 98.17,65.75 94.61,69.3 92.83,69.3 92.83,68.8 R4.15
  Bottom 0.254: v115.44,27.65 114.42,28.66 v105.53,28.66 | v98.42,35.27 v101.47,35.27
P10  (via drill 0.61)
  Top 0.254: v115.95,31.71 115.95,29.93 116.45,29.43 U$1.11 | v117.72,41.11 117.72,69.81 109.09,69.81 108.58,69.3 108.58,64.73 111.12,64.73 111.88,65.49 111.88,66.76 R5.15
  Bottom 0.254: v115.95,31.71 115.44,31.2 114.68,31.2 113.91,30.44 113.91,29.17 120.77,29.17 126.36,34.76 | 126.36,34.76 126.87,35.27 | v117.72,41.11 118.99,42.38 131.44,42.38 132.71,41.11 132.71,34.76 126.36,34.76
P13
  Top 0.254: U$1.14 118.49,32.47 120.26,32.47 120.26,37.05 132.96,49.75 132.96,65.24 134.49,66.76 R6.15
P14  (via drill 0.61)
  Top 0.254: v114.93,33.24 117.72,33.24 U$1.15 | v90.55,35.27 89.53,36.28 89.53,63.46 91.56,65.49 91.56,66.76 R4.14
  Bottom 0.254: v114.93,33.24 92.58,33.24 v90.55,35.27
P15  (via drill 0.61)
  Top 0.254: v120.77,60.41 120.77,38.32 119.76,37.3 119.76,34 118.49,34 U$1.16 | v110.87,65.75 110.61,66 110.61,66.76 R5.14
  Bottom 0.254: v120.77,60.41 115.44,65.75 v110.87,65.75
P18
  Top 0.254: U$1.21 118.49,38.06 119.76,38.06 119.76,63.46 125.6,69.3 133.22,69.3 133.22,68.8 R6.14
P19  (via drill 0.61)
  Top 0.254: v118.74,58.64 118.74,39.08 118.49,38.82 U$1.22 | v102.48,60.92 99.94,63.46 v99.94,66 | v90.55,65.75 90.29,66 90.29,66.76 R4.13
  Bottom 0.254: v118.74,58.64 116.45,60.92 v102.48,60.92 | v99.94,66 99.69,65.75 v90.55,65.75
P20
  Top 0.254: U$1.23 116.45,40.86 116.71,41.11 116.71,56.1 114.68,58.13 114.68,68.29 113.66,69.3 109.34,69.3 109.34,68.8 R5.13
P23  (via drill 0.61)
  Top 0.254: v114.68,39.33 113.91,40.09 U$1.26 | v122.3,44.16 130.42,52.29 130.42,65.24 131.95,66.76 R6.13
  Bottom 0.254: v114.68,39.33 119.5,44.16 v122.3,44.16
P24  (via drill 0.61)
  Top 0.254: v110.1,42.13 110.1,40.86 U$1.31 | v89.28,65.75 89.02,66 89.02,66.76 R4.12
  Bottom 0.254: v110.1,42.13 112.64,44.67 119.5,44.67 124.33,49.49 124.33,52.54 114.42,52.54 112.64,54.32 103.25,54.32 98.67,58.89 98.67,64.48 90.55,64.48 v89.28,65.75
P25
  Top 0.254: U$1.32 109.09,40.86 109.09,47.97 107.56,49.49 107.56,66.51 107.82,66.76 R5.12
P28  (via drill 0.61)
  Top 0.254: v106.04,45.68 106.04,44.67 105.53,44.16 105.53,38.06 106.29,38.06 U$1.35 | R1.2 98.93,20.28 99.44,20.79 99.44,45.17 101.21,46.95 IC4.6
  Bottom 0.254: v106.04,45.68 104.52,47.21 103.5,47.21 IC4.6
P29  (via drill 0.61)
  Top 0.254: R2.2 98.93,16.47 99.94,17.49 99.94,43.14 101.21,44.41 IC4.5 | v105.02,44.92 105.02,37.3 106.29,37.3 U$1.36 | v121.79,48.22 129.92,56.35 129.92,66 130.68,66.76 R6.12
  Bottom 0.254: IC4.5 v105.02,44.92 105.28,44.67 106.29,44.67 108.33,46.7 120.26,46.7 v121.79,48.22
P30  (via drill 0.61)
  Top 0.254: v105.02,35.78 105.02,36.28 106.29,36.28 U$1.37
  Bottom 0.254: v105.02,35.78 104.52,36.28 90.29,36.28 86.99,32.98 86.99,31.71 104.26,31.71 104.77,32.22 106.55,32.22 107.56,31.2 113.91,31.2 114.93,32.22 115.18,32.22 117.22,34.25 117.22,35.52 116.71,35.52 115.95,36.28 115.95,37.55 128.65,37.55 128.9,37.3 131.44,37.3 132.2,38.06 132.2,40.6 131.44,40.6 PROP_PLUG.4
P31  (via drill 0.61)
  Top 0.254: v108.07,37.81 108.07,35.52 107.06,35.52 U$1.38
  Bottom 0.254: v108.07,37.81 108.33,38.06 128.9,38.06 PROP_PLUG.3
PWM1  (via drill 0.61)
  Top 0.254: v109.85,3.77 109.85,19.77 110.61,20.54 110.61,28.41 110.87,28.66 U$1.4
  Bottom 0.254: v109.85,3.77 109.34,3.26 90.8,3.26 90.55,3.01 41.78,3.01 16.38,28.41 IC1.5
PWM2  (via drill 0.61)
  Top 0.254: v113.41,9.87 113.41,11.39 114.68,12.66 114.68,20.28 116.96,22.57 116.96,30.95 117.47,31.46 117.72,31.46 U$1.13
  Bottom 0.254: IC1.10 22.73,33.49 23.49,32.73 24.76,32.73 24.76,28.41 44.57,8.6 100.45,8.6 100.45,5.3 101.98,3.77 108.83,3.77 108.83,5.3 v113.41,9.87
PWM3  (via drill 0.61)
  Top 0.254: v113.91,37.05 113.91,37.55 117.22,37.55 117.47,37.3 117.72,37.3 U$1.20 | v76.32,36.28 74.8,37.81 v74.8,38.32
  Bottom 0.254: IC2.5 43.81,34.76 46.86,37.81 74.29,37.81 v74.8,38.32 | v113.91,37.05 113.66,36.79 76.83,36.79 v76.32,36.28
PWM4  (via drill 0.61)
  Top 0.254: v51.43,23.33 47.62,27.14 47.62,30.95 46.35,32.22 46.35,35.27 v46.1,35.52 | v113.66,52.03 113.66,48.22 113.91,47.97 113.91,45.43 114.68,44.67 114.68,40.86 U$1.25 | v100.71,53.81 99.44,55.08 99.44,65.24 93.34,71.34 76.83,71.34 76.83,78.19 76.07,78.96 47.87,78.96 47.87,69.3 48.64,68.54 52.7,68.54 52.7,65.24 58.29,59.65 58.29,42.38 50.67,34.76 IC2.10
  Bottom 0.254: v46.1,35.52 48.89,35.52 49.65,34.76 IC2.10 | v113.66,52.03 111.88,53.81 v100.71,53.81
PWM5  (via drill 0.61)
  Top 0.254: v106.55,39.84 106.55,38.82 U$1.34 | v94.61,39.84 93.09,38.32 v93.09,27.65
  Bottom 0.254: IC3.5 73.53,27.14 74.29,26.38 91.82,26.38 v93.09,27.65 | v94.61,39.84 v106.55,39.84
PWM6  (via drill 0.61)
  Top 0.254: v105.53,29.93 106.29,30.7 U$1.44
  Bottom 0.254: v105.53,29.93 105.28,30.19 86.48,30.19 86.23,30.44 81.66,30.44
  Bottom 0.813: 81.66,30.44 79.88,32.22 IC3.10
RES  (via drill 0.61)
  Top 0.254: v113.41,27.65 113.41,28.41 113.15,28.66 U$1.7 | PROP_PLUG.2 128.9,35.52 125.85,32.47 125.85,27.39 RESET.P$1 125.34,25.87 125.34,21.04 RESET.P$2
  Bottom 0.254: v113.41,27.65 114.42,26.63 124.58,26.63 RESET.P$1
SEN_1
  Bottom 0.254: IC1.1 10.79,36.03 12.06,37.3 24.76,37.3 48.13,60.67 82.16,60.67 82.67,61.18 SEN_EN.1
SEN_2  (via drill 0.61)
  Top 0.254: v29.33,67.53 29.84,67.02 29.84,31.71 29.08,30.95 IC1.15
  Bottom 0.254: v29.33,67.53 34.16,62.7 84.2,62.7 85.21,61.68 SEN_EN.3
SEN_3  (via drill 0.61)
  Top 0.254: v43.3,63.72 43.05,63.46 43.05,35.52 43.81,34.76 43.81,32.22 42.03,30.44 39.24,30.44 39.24,29.68 IC2.1
  Bottom 0.254: v43.3,63.72 85.72,63.72 87.75,61.68 SEN_EN.5
SEN_4  (via drill 0.61)
  Top 0.254: v59.3,51.27 58.8,50.76 v58.8,31.46
  Bottom 0.254: v59.3,51.27 68.19,60.16 89.28,60.16 90.29,61.18 SEN_EN.7 | v58.8,31.46 57.02,29.68 IC2.15
SEN_5  (via drill 0.61)
  Top 0.254: v92.07,25.36 92.07,59.91 93.09,60.92 SEN_EN.9
  Bottom 0.254: v92.07,25.36 91.56,25.87 69.72,25.87 68.45,27.14 IC3.1
SEN_6
  Top 0.254: SEN_EN.11 95.63,61.94 92.07,65.49 92.07,69.3 84.45,69.3 84.45,53.81 87.5,50.76 87.5,40.6 85.21,38.32 85.21,38.06 83.18,36.03 83.18,31.71 85.21,29.68 IC3.15
VCC3.3V2  (via drill 0.61)
  Top 0.254: v100.96,40.86 100.45,40.35 100.45,12.15 99.94,11.65 X1.2
  Bottom 0.254: v100.96,40.86 92.83,40.86 92.83,50.51 93.34,51.02 99.69,51.02 100.96,52.29 IC4.8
